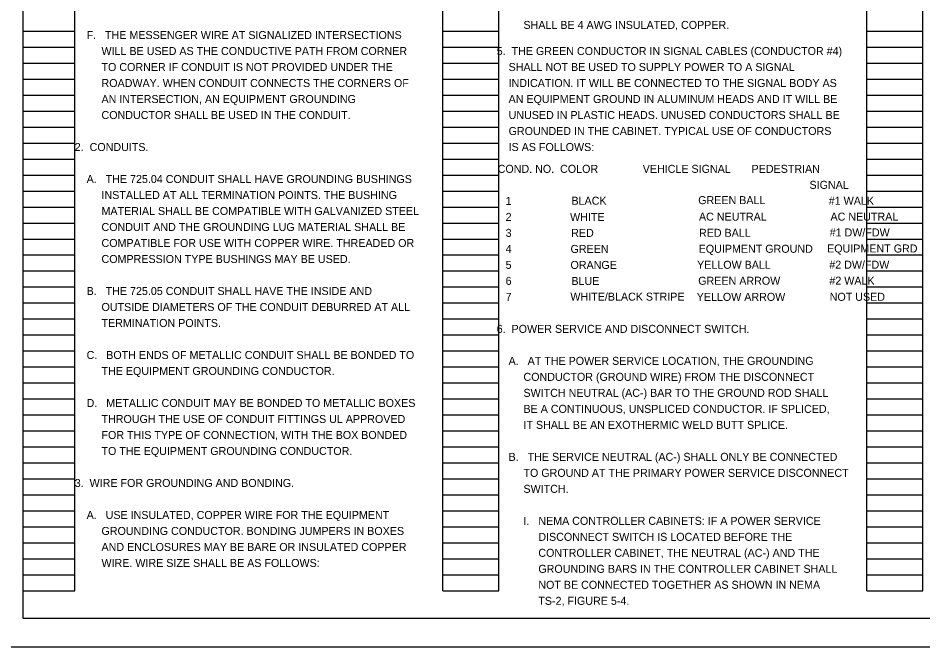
# Model space of a CAD drawing. Extents: x -18.7 to 62.3, y -3.1 to 33.6.
# Drawn here: x 1.91 to 17.74, y 0 to 11.01 of the extents above; entities that cross this region are included whole.
import ezdxf

# ---------------------------------------------------------------- set-up
doc = ezdxf.new("R2010")
doc.units = 0
for name, color, linetype in [('SH_Border', 7, 'Continuous'), ('SH_Cut_Line', 7, 'Continuous'), ('SH_Data', 7, 'Continuous'), ('SH_Text', 7, 'Continuous')]:
    doc.layers.add(name, color=color, linetype=linetype)

msp = doc.modelspace()

# ---------------------------------------------------------------- linework, layer by layer
at = {"layer": 'SH_Border'}
msp.add_lwpolyline([(2.001, 21.5), (33.501, 21.5), (33.501, 0.5), (2.001, 0.5)], close=True, dxfattribs=at)
at = {"layer": 'SH_Cut_Line'}
msp.add_lwpolyline([(0.001, 0), (34.001, 0), (34.001, 22), (0.001, 22)], close=True, dxfattribs=at)
at = {"layer": 'SH_Data'}
for p, q in [((2.001, 0.98), (2.001, 21.14)), ((2.901, 0.98), (2.901, 21.14)), ((9.341, 0.98), (9.341, 21.14)), ((10.321, 0.98), (10.321, 21.14)), ((16.761, 0.98), (16.761, 21.14)), ((17.741, 0.98), (17.741, 21.14)), ((2.001, 10.78), (2.901, 10.78)), ((9.341, 10.78), (10.321, 10.78)), ((16.761, 10.78), (17.741, 10.78)), ((2.001, 10.5), (2.901, 10.5)), ((9.341, 10.5), (10.321, 10.5)), ((16.761, 10.5), (17.741, 10.5)), ((2.001, 10.22), (2.901, 10.22)), ((9.341, 10.22), (10.321, 10.22)), ((16.761, 10.22), (17.741, 10.22)), ((2.001, 9.94), (2.901, 9.94)), ((9.341, 9.94), (10.321, 9.94)), ((16.761, 9.94), (17.741, 9.94)), ((2.001, 9.66), (2.901, 9.66)), ((9.341, 9.66), (10.321, 9.66)), ((16.761, 9.66), (17.741, 9.66)), ((2.001, 9.38), (2.901, 9.38)), ((9.341, 9.38), (10.321, 9.38)), ((16.761, 9.38), (17.741, 9.38)), ((2.001, 9.1), (2.901, 9.1)), ((9.341, 9.1), (10.321, 9.1)), ((16.761, 9.1), (17.741, 9.1)), ((2.001, 8.82), (2.901, 8.82)), ((9.341, 8.82), (10.321, 8.82)), ((16.761, 8.82), (17.741, 8.82)), ((2.001, 8.54), (2.901, 8.54)), ((9.341, 8.54), (10.321, 8.54)), ((16.761, 8.54), (17.741, 8.54)), ((2.001, 8.26), (2.901, 8.26)), ((9.341, 8.26), (10.321, 8.26)), ((16.761, 8.26), (17.741, 8.26)), ((2.001, 7.98), (2.901, 7.98)), ((9.341, 7.98), (10.321, 7.98)), ((16.761, 7.98), (17.741, 7.98)), ((2.001, 7.7), (2.901, 7.7)), ((9.341, 7.7), (10.321, 7.7)), ((16.761, 7.7), (17.741, 7.7)), ((2.001, 7.42), (2.901, 7.42)), ((9.341, 7.42), (10.321, 7.42)), ((16.761, 7.42), (17.741, 7.42)), ((2.001, 7.14), (2.901, 7.14)), ((9.341, 7.14), (10.321, 7.14)), ((16.761, 7.14), (17.741, 7.14)), ((2.001, 6.86), (2.901, 6.86)), ((9.341, 6.86), (10.321, 6.86)), ((16.761, 6.86), (17.741, 6.86)), ((2.001, 6.58), (2.901, 6.58)), ((9.341, 6.58), (10.321, 6.58)), ((16.761, 6.58), (17.741, 6.58)), ((2.001, 6.3), (2.901, 6.3)), ((9.341, 6.3), (10.321, 6.3)), ((16.761, 6.3), (17.741, 6.3)), ((2.001, 6.02), (2.901, 6.02)), ((9.341, 6.02), (10.321, 6.02)), ((16.761, 6.02), (17.741, 6.02)), ((2.001, 5.74), (2.901, 5.74)), ((9.341, 5.74), (10.321, 5.74)), ((16.761, 5.74), (17.741, 5.74)), ((2.001, 5.46), (2.901, 5.46)), ((9.341, 5.46), (10.321, 5.46)), ((16.761, 5.46), (17.741, 5.46)), ((2.001, 5.18), (2.901, 5.18)), ((9.341, 5.18), (10.321, 5.18)), ((16.761, 5.18), (17.741, 5.18)), ((2.001, 4.9), (2.901, 4.9)), ((9.341, 4.9), (10.321, 4.9)), ((16.761, 4.9), (17.741, 4.9)), ((2.001, 4.62), (2.901, 4.62)), ((9.341, 4.62), (10.321, 4.62)), ((16.761, 4.62), (17.741, 4.62)), ((2.001, 4.34), (2.901, 4.34)), ((9.341, 4.34), (10.321, 4.34)), ((16.761, 4.34), (17.741, 4.34)), ((2.001, 4.06), (2.901, 4.06)), ((9.341, 4.06), (10.321, 4.06)), ((16.761, 4.06), (17.741, 4.06)), ((2.001, 3.78), (2.901, 3.78)), ((9.341, 3.78), (10.321, 3.78)), ((16.761, 3.78), (17.741, 3.78)), ((2.001, 3.5), (2.901, 3.5)), ((9.341, 3.5), (10.321, 3.5)), ((16.761, 3.5), (17.741, 3.5)), ((2.001, 3.22), (2.901, 3.22)), ((9.341, 3.22), (10.321, 3.22)), ((16.761, 3.22), (17.741, 3.22)), ((2.001, 2.94), (2.901, 2.94)), ((9.341, 2.94), (10.321, 2.94)), ((16.761, 2.94), (17.741, 2.94)), ((2.001, 2.66), (2.901, 2.66)), ((9.341, 2.66), (10.321, 2.66)), ((16.761, 2.66), (17.741, 2.66)), ((2.001, 2.38), (2.901, 2.38)), ((9.341, 2.38), (10.321, 2.38)), ((16.761, 2.38), (17.741, 2.38)), ((2.001, 2.1), (2.901, 2.1)), ((9.341, 2.1), (10.321, 2.1)), ((16.761, 2.1), (17.741, 2.1)), ((2.001, 1.82), (2.901, 1.82)), ((9.341, 1.82), (10.321, 1.82)), ((16.761, 1.82), (17.741, 1.82)), ((2.001, 1.54), (2.901, 1.54)), ((9.341, 1.54), (10.321, 1.54)), ((16.761, 1.54), (17.741, 1.54)), ((2.001, 1.26), (2.901, 1.26)), ((9.341, 1.26), (10.321, 1.26)), ((16.761, 1.26), (17.741, 1.26)), ((2.001, 0.98), (2.901, 0.98)), ((9.341, 0.98), (10.321, 0.98)), ((16.761, 0.98), (17.741, 0.98))]:
    msp.add_line(p, q, dxfattribs=at)

# ---------------------------------------------------------------- texts
at = {"layer": 'SH_Text'}
for s, p in [('         SHALL BE 4 AWG INSULATED, COPPER.', (10.284, 10.817)), ('    F.   THE MESSENGER WIRE AT SIGNALIZED INTERSECTIONS', (2.901, 10.64)), ('         WILL BE USED AS THE CONDUCTIVE PATH FROM CORNER', (2.901, 10.36)), ('5.  THE GREEN CONDUCTOR IN SIGNAL CABLES (CONDUCTOR #4)', (10.284, 10.36)), ('         TO CORNER IF CONDUIT IS NOT PROVIDED UNDER THE', (2.901, 10.08)), ('    SHALL NOT BE USED TO SUPPLY POWER TO A SIGNAL', (10.284, 10.08)), ('         ROADWAY. WHEN CONDUIT CONNECTS THE CORNERS OF', (2.901, 9.8)), ('    INDICATION. IT WILL BE CONNECTED TO THE SIGNAL BODY AS', (10.284, 9.8)), ('         AN INTERSECTION, AN EQUIPMENT GROUNDING', (2.901, 9.52)), ('    AN EQUIPMENT GROUND IN ALUMINUM HEADS AND IT WILL BE', (10.284, 9.52)), ('         CONDUCTOR SHALL BE USED IN THE CONDUIT.', (2.901, 9.24)), ('    UNUSED IN PLASTIC HEADS. UNUSED CONDUCTORS SHALL BE', (10.284, 9.24)), ('    GROUNDED IN THE CABINET. TYPICAL USE OF CONDUCTORS', (10.284, 8.96)), ('2.  CONDUITS.', (2.901, 8.68)), ('    IS AS FOLLOWS:', (10.284, 8.68)), ('COND. NO.  COLOR               VEHICLE SIGNAL       PEDESTRIAN ', (10.301, 8.298)), ('    A.   THE 725.04 CONDUIT SHALL HAVE GROUNDING BUSHINGS', (2.901, 8.12)), ('        SIGNAL', (15.341, 8.018)), ('         INSTALLED AT ALL TERMINATION POINTS. THE BUSHING', (2.901, 7.84)), ('   1          ', (10.284, 7.737)), ('BLACK', (11.592, 7.74)), ('GREEN BALL', (13.81, 7.75)), ('#1 WALK', (16.094, 7.739)), ('         MATERIAL SHALL BE COMPATIBLE WITH GALVANIZED STEEL', (2.901, 7.56)), ('AC NEUTRAL', (13.823, 7.461)), ('AC NEUTRAL', (16.124, 7.461)), ('   2         ', (10.284, 7.457)), ('WHITE', (11.568, 7.455)), ('         CONDUIT AND THE GROUNDING LUG MATERIAL SHALL BE', (2.901, 7.28)), ('   3         ', (10.284, 7.177)), ('RED', (11.587, 7.177)), ('RED BALL', (13.823, 7.178)), ('#1 DW/FDW', (16.11, 7.185)), ('         COMPATIBLE FOR USE WITH COPPER WIRE. THREADED OR', (2.901, 7)), ('   4         ', (10.284, 6.897)), ('GREEN', (11.576, 6.896)), ('EQUIPMENT GROUND', (13.818, 6.899)), ('EQUIPMENT GRD', (16.065, 6.904)), ('         COMPRESSION TYPE BUSHINGS MAY BE USED.', (2.901, 6.72)), ('   5         ', (10.284, 6.617)), ('ORANGE', (11.575, 6.616)), ('YELLOW BALL', (13.79, 6.619)), ('#2 DW/FDW', (16.103, 6.621)), ('   6         ', (10.284, 6.337)), ('BLUE', (11.591, 6.335)), ('GREEN ARROW', (13.81, 6.339)), ('#2 WALK', (16.105, 6.341)), ('    B.   THE 725.05 CONDUIT SHALL HAVE THE INSIDE AND', (2.901, 6.16)), ('   7         ', (10.284, 6.057)), ('WHITE/BLACK STRIPE', (11.573, 6.061)), ('YELLOW ARROW', (13.783, 6.057)), ('NOT USED', (16.11, 6.058)), ('         OUTSIDE DIAMETERS OF THE CONDUIT DEBURRED AT ALL', (2.901, 5.88)), ('         TERMINATION POINTS.', (2.901, 5.6)), ('6.  POWER SERVICE AND DISCONNECT SWITCH.', (10.284, 5.497)), ('    C.   BOTH ENDS OF METALLIC CONDUIT SHALL BE BONDED TO', (2.901, 5.04)), ('    A.   AT THE POWER SERVICE LOCATION, THE GROUNDING', (10.284, 4.937)), ('         THE EQUIPMENT GROUNDING CONDUCTOR.', (2.901, 4.76)), ('         CONDUCTOR (GROUND WIRE) FROM THE DISCONNECT', (10.284, 4.657)), ('         SWITCH NEUTRAL (AC-) BAR TO THE GROUND ROD SHALL', (10.284, 4.377)), ('    D.   METALLIC CONDUIT MAY BE BONDED TO METALLIC BOXES', (2.901, 4.2)), ('         BE A CONTINUOUS, UNSPLICED CONDUCTOR. IF SPLICED,', (10.284, 4.097)), ('         THROUGH THE USE OF CONDUIT FITTINGS UL APPROVED', (2.901, 3.92)), ('         IT SHALL BE AN EXOTHERMIC WELD BUTT SPLICE.', (10.284, 3.817)), ('         FOR THIS TYPE OF CONNECTION, WITH THE BOX BONDED', (2.901, 3.64)), ('         TO THE EQUIPMENT GROUNDING CONDUCTOR.', (2.901, 3.36)), ('    B.   THE SERVICE NEUTRAL (AC-) SHALL ONLY BE CONNECTED', (10.284, 3.257)), ('         TO GROUND AT THE PRIMARY POWER SERVICE DISCONNECT', (10.284, 2.977)), ('3.  WIRE FOR GROUNDING AND BONDING.', (2.901, 2.8)), ('         SWITCH.', (10.284, 2.697)), ('    A.   USE INSULATED, COPPER WIRE FOR THE EQUIPMENT', (2.901, 2.24)), ('         I.   NEMA CONTROLLER CABINETS: IF A POWER SERVICE', (10.284, 2.137)), ('         GROUNDING CONDUCTOR. BONDING JUMPERS IN BOXES', (2.901, 1.96)), ('              DISCONNECT SWITCH IS LOCATED BEFORE THE', (10.284, 1.857)), ('         AND ENCLOSURES MAY BE BARE OR INSULATED COPPER', (2.901, 1.68)), ('              CONTROLLER CABINET, THE NEUTRAL (AC-) AND THE', (10.284, 1.577)), ('         WIRE. WIRE SIZE SHALL BE AS FOLLOWS:', (2.901, 1.4)), ('              GROUNDING BARS IN THE CONTROLLER CABINET SHALL', (10.284, 1.297)), ('              NOT BE CONNECTED TOGETHER AS SHOWN IN NEMA', (10.284, 1.017)), ('              TS-2, FIGURE 5-4.', (10.284, 0.737))]:
    msp.add_text(s, height=0.14, dxfattribs=at).set_placement(p)

doc.saveas('drawing.dxf')
